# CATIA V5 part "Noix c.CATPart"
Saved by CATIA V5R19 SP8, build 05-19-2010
Part number: Noix c
Bounding box of the stored display mesh (mm): x -71 to 91.36, y -4.855 to 29.866, z -28.303 to 30.696
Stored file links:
  F:\CFAO\Hberriche\Noix c.CATPart
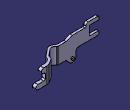
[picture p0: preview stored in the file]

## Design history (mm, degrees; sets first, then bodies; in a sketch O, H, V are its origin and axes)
Body1 (main body)
  Sketch1 on zx-plane, origin (0, 0, 0), H (-1, 0, 0), V (0, 0, 1)
    point P1 (43, 22.6962)
    line L1 (43, 24.6962) -> (43, 25.6962)
    point P2 (43, 30.6962)
    line L2 (48, 30.6962) -> (69, 30.6962)
    point P3 (71, 30.6962)
    line L3 (71, 28.6962) -> (71, 23.6962)
    point P4 (71, 22.6962)
    line L4 (70, 22.6962) -> (52, 22.6962)
    point P5 (50, 22.6962)
    line L5 (50, 20.6962) -> (50, 4.6962)
    line L6 (52, 2.6962) -> (70, 2.6962)
    point P6 (71, 2.6962)
    line L7 (71, 1.6962) -> (71, -3.3038)
    point P7 (71, -5.3038)
    line L8 (69, -5.3038) -> (26, -5.3038)
    point P8 (21, -5.3038)
    line L9 (21, -10.3038) -> (21, -20.3038)
    point P9 (21, -20.3038)
    arc A1 centre (26, -10.3038) radius 5 from (26, -5.3038) to (21, -10.3038) ccw
    line L10 (0, -17.5) -> (0, 17.5)
    point P13 (0, -17.5)
    line L11 (0, 17.5) -> (13, 22.6962)
    point P15 (13, 22.6962)
    line L12 (41, 22.6962) -> (13, 22.6962)
    point P16 (13, 22.6962)
    line L13 (0, -17.5) -> (7.2013, -25.8152)
    arc A2 centre (13, -20.3038) radius 8 from (7.2013, -25.8152) to (21, -20.3038) ccw
    point P18 (13, -20.3038)
    arc A3 centre (69, 28.6962) radius 2 from (69, 30.6962) to (71, 28.6962) cw
    arc A4 centre (48, 25.6962) radius 5 from (48, 30.6962) to (43, 25.6962) ccw
    arc A5 centre (70, 23.6962) radius 1 from (70, 22.6962) to (71, 23.6962) ccw
    arc A6 centre (52, 20.6962) radius 2 from (52, 22.6962) to (50, 20.6962) ccw
    arc A7 centre (52, 4.6962) radius 2 from (50, 4.6962) to (52, 2.6962) ccw
    arc A8 centre (70, 1.6962) radius 1 from (70, 2.6962) to (71, 1.6962) cw
    arc A9 centre (69, -3.3038) radius 2 from (69, -5.3038) to (71, -3.3038) ccw
    arc A10 centre (41, 24.6962) radius 2 from (41, 22.6962) to (43, 24.6962) ccw
    distance L6 L4 = 20
    distance P7 P8 = 50
    distance P8 P9 = 15
    radius A1 = 5
    length L10 = 35
    distance L5 L10 = 50
    length L11 = 14
    length L13 = 11
    distance L10 P18 = 13
    distance P13 H = 17.5
    distance P2 P3 = 28
    distance P3 P4 = 8
    radius A3 = 2
    radius A4 = 5
    distance P4 P5 = 21
    radius A5 = 1
    radius A6 = 2
    radius A7 = 2
    distance P6 P7 = 8
    radius A8 = 1
    radius A9 = 2
    distance P1 P16 = 30
    radius A10 = 2
    vertical: L1 V, L3 V, L5 V, L7 V, L9 V, L10 V
    horizontal: L2 H, L4 H, L6 H, L8 H, L12 H
    coincidence: P6 L3, L8 P8, L9 P8, P15 L4, P16 L11, P15 P16, L10 V, L2 P3, L3 P3, L2 P2, L1 P2, L4 P4, L3 P4, L4 P5, L5 P5, L6 P6, L7 P6, L8 P7, L7 P7, L12 P1, L1 P1
    tangency: A1 L8, A1 L9, A2 L9, A3 L2, A3 L3, A4 L2, A4 L1, A5 L4, A5 L3, A6 L4, A6 L5, A7 L5, A7 L6, A8 L6, A8 L7, A9 L8, A9 L7, A10 L12, A10 L1
  Pad1: profile Sketch1, direction (0, 1, 0), length 5
  Sketch2 on xy-plane, origin (0, 0, 0), H (1, 0, 0), V (0, 1, 0)
    point P1 (0, 5)
    line L1 (0, 5) -> (19.6224, 5)
    point P2 (19.6224, 5)
    point P3 (19.6224, 5)
    arc A1 centre (27, 7.3403) radius 7.7399 from (19.6224, 5) to (31.9311, 1.3745) ccw
    point P4 (27, 7.3403)
    point P5 (31.9311, 1.3745)
    point P6 (36.7384, 0)
    line L2 (31.9311, 1.3745) -> (44.8037, 12.0146)
    point P7 (46.9812, 13.8144)
    line L3 (36.7384, 0) -> (49.6953, 10.2124)
    point P8 (51.9812, 12.0141)
    line L4 (46.9812, 16.6393) -> (46.9812, 18.1342)
    point P9 (46.9812, 19.8144)
    line L5 (48.4137, 20.6922) -> (60.4991, 28.0976)
    point P10 (59.771, 27.6514)
    line L6 (51.9812, 14.9247) -> (51.9812, 15.334)
    point P11 (51.9812, 12.0141)
    point P12 (51.9812, 17.0141)
    line L7 (53.4137, 17.8919) -> (58.4749, 20.9932)
    point P13 (61.3604, 22.7613)
    line L8 (64.7445, 22.7613) -> (91.3604, 22.7613)
    point P14 (91.3604, 22.7613)
    line L9 (66.7688, 29.8657) -> (91.3604, 29.8657)
    point P15 (63.3847, 29.8657)
    line L10 (91.3604, 29.8657) -> (91.3604, 22.7613)
    reference projected line E1 (-13, 5) -> (0, 5) from edge [face of Pad1 from Sketch1.L11 | end face of Pad1]
    arc A2 centre (49.9812, 18.1342) radius 3 from (46.9812, 18.1342) to (48.4137, 20.6922) cw
    arc A3 centre (66.7688, 17.8657) radius 12 from (60.4991, 28.0976) to (66.7688, 29.8657) cw
    arc A4 centre (64.7445, 10.7613) radius 12 from (58.4749, 20.9932) to (64.7445, 22.7613) cw
    arc A5 centre (54.9812, 15.334) radius 3 from (53.4137, 17.8919) to (51.9812, 15.334) ccw
    arc A6 centre (40.9812, 16.6393) radius 6 from (44.8037, 12.0146) to (46.9812, 16.6393) ccw
    arc A7 centre (45.9812, 14.9247) radius 6 from (51.9812, 14.9247) to (49.6953, 10.2124) cw
    reference projected point E2 (27, 7.3403) from edge of DatumCurve1
    line L11 (0, 5) -> (0, 0)
    point P35 (0, 0)
    line L12 (0, 0) -> (17.2616, 0)
    arc A8 centre (27, 7.3403) radius 12.195 from (17.2616, 0) to (36.7384, 0) ccw
    point P37 (27, 7.3403)
    point P38 (36.7384, 0)
    distance P6 P5 = 5
    distance L6 L4 = 5
    distance L7 L5 = 5
    distance P7 P9 = 6
    distance P9 P10 = 15
    radius A2 = 3
    radius A3 = 12
    distance P12 P13 = 11
    distance P13 P14 = 30
    radius A4 = 12
    distance P11 P12 = 5
    radius A5 = 3
    radius A6 = 6
    radius A7 = 6
    distance P4 E2 = 0
    coincidence: P1 V, P11 P8, P15 L5, E1 L1, L4 P9, L5 P9, L5 P10, L9 P15, L7 P13, L8 P13, L7 P12, L6 P12, L2 P7, L4 P7, L6 P11, L3 P8, P2 P3, A8 P6, P38 H, P38 P6, P4 P37, P35 O
    horizontal: L1 H, L8 H, L9 H, L12 H
    tangency: L2 A1, A2 L4, A2 L5, A3 L5, A3 L9, A4 L7, A4 L8, A5 L7, A5 L6, A6 L2, A6 L4, A7 L6, A7 L3
    vertical: L4 V, L6 V, L10 V, L11 V
  Pad2: profile Sketch2, direction (0, 0, 1), length 17.5, mirrored extent
  Sketch3 on face of Pad2, origin (0, 5, 0), H (-1, 0, 0), V (0, 0, 1)
    circle A1 centre (13.0767, -19.9727) radius 3
    radius A1 = 3
  Pad3: profile Sketch3, direction (0, 1, 0), length 2
  Fillet1: radius 3, on edge [face of Pad2 | face of Pad2 from Sketch2.A1]
  Sketch4 on face of Pad2 from Sketch2.L8, origin (0, 22.7613, 0), H (1, 0, 0), V (0, 0, 1)
    point P1 (91.3604, 17.5)
    line L1 (70.2698, 7.5) -> (70.2698, -7.5)
    line L2 (70.2698, -7.5) -> (91.3604, -7.5)
    line L3 (91.3604, 17.5) -> (91.3604, -7.5)
    reference projected line E1 (91.3604, -17.5) -> (91.3604, 17.5) from edge [face of Pad2 from Sketch2.L10 | face of Pad2 from Sketch2.L8]
    reference projected line E2 (64.7445, -17.5) -> (91.3604, -17.5) from edge [start face of Pad2 | face of Pad2 from Sketch2.L8]
    line L4 (70.2698, 7.5) -> (78.7649, 7.5)
    line L5 (78.7649, 7.5) -> (78.7649, 17.5)
    line L6 (78.7649, 17.5) -> (91.3604, 17.5)
    point P7 (91.3604, 17.5)
    distance L2 E2 = 10
    length L5 = 10
    length L1 = 15
    vertical: L1 V, L3 V, L5 V
    horizontal: L2 H, L4 H, L6 H
    coincidence: E1 L3, P7 L3, P1 P7
  Pocket1: profile Sketch4, direction (0, 1, 0), through (limit type 3)
  Fillet2: radius 5, on edge [face of Pocket1 from Sketch4.L4 | face of Pocket1 from Sketch4.L5]; edge [face of Pocket1 from Sketch4.L5 | end face of Pad2]; edge [face of Pad2 from Sketch2.L10 | face of Pocket1 from Sketch4.L2]; edge [start face of Pad2 | face of Pad2 from Sketch2.L10]
  Fillet3: radius 3, on edge [face of Pocket1 from Sketch4.L2 | face of Pocket1 from Sketch4.L1]
  DatumSurface1
  Fillet4: radius 3, on edge [face of Pocket1 from Sketch4.L1 | face of Pocket1 from Sketch4.L4]
  Sketch5 on face of Pad1 from Sketch1.L6, origin (0, 0, 2.6962), H (1, 0, 0), V (0, 1, 0)
    line L1 (-69.0003, 2.5) -> (-47.9399, 2.5)
    reference projected line E1 (-69, 5) -> (-48, 5) from edge [face of Pad1 from Sketch1.L2 | end face of Pad1]
    distance E1 L1 = 2.5
    horizontal: L1 H
  Sketch6 on end face of Pad2, origin (0, 0, 17.5), H (1, 0, 0), V (0, 1, 0)
    point P1 (27, 7.3403)
    reference projected arc E1 centre (27, 7.3403) radius 7.7399 from (19.6224, 5) to (31.9311, 1.3745) ccw from edge [face of Pad2 from Sketch2.A1 | end face of Pad2]
    concentricity: E1 P1
  Plane1: type Tangent, Support end face of Pad2, RefPoint Sketch6
  DatumCurve1
  DatumSurface2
